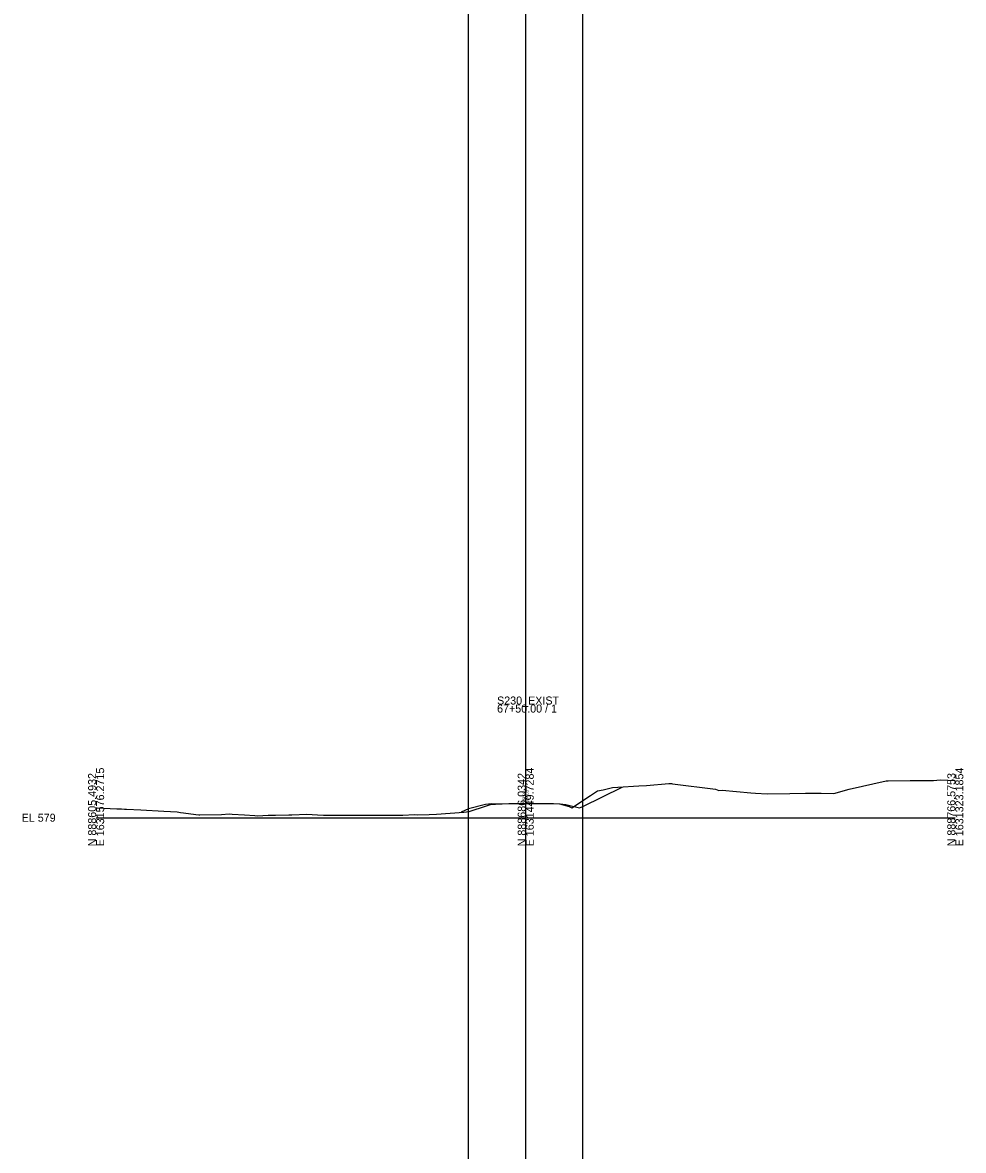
# Model space of a CAD drawing. Extents: x 1631115 to 1631443, y 885974 to 892071.
# Drawn here: x 1631114.8 to 1631443.3, y 886367.5 to 886761.1 of the extents above; entities that cross this region are included whole.
import ezdxf

# ---------------------------------------------------------------- set-up
doc = ezdxf.new("R2010")
doc.units = 0
for name, color, linetype in [('Default', 7, 'Continuous'), ('RD_GPK_XS_Cell', 7, 'Continuous'), ('RD_XS_EarthShd', 7, 'Continuous'), ('RD_XS_ExGround', 7, 'Continuous'), ('RD_XS_Pave', 7, 'Continuous'), ('RD_XS_TieSlope', 7, 'Continuous'), ('RD_XS_TX_Elev_EX', 7, 'Continuous'), ('RD_XS_TX_Elev_PR', 7, 'Continuous')]:
    doc.layers.add(name, color=color, linetype=linetype)

msp = doc.modelspace()

# ---------------------------------------------------------------- linework, layer by layer
at = {"layer": 'Default'}
for p, q in [((1631270.47, 885983.65), (1631270.47, 892068.63)), ((1631290.47, 885983.65), (1631290.47, 892068.63)), ((1631310.47, 885983.65), (1631310.47, 892068.63))]:
    msp.add_line(p, q, dxfattribs=at)
at = {"layer": 'RD_GPK_XS_Cell'}
for p, q in [((1631290.47, 886483.65), (1631290.47, 886523.14)), ((1631140.47, 886483.65), (1631290.47, 886483.65)), ((1631290.47, 886483.65), (1631440.47, 886483.65))]:
    msp.add_line(p, q, dxfattribs=at)
at = {"layer": 'RD_XS_EarthShd'}
for p, q in [((1631278.47, 886488.46), (1631276.47, 886488.3)), ((1631302.47, 886488.46), (1631304.47, 886488.3))]:
    msp.add_line(p, q, dxfattribs=at)
at = {"layer": 'RD_XS_ExGround'}
msp.add_lwpolyline([(1631140.47, 886487.07), (1631140.81, 886487.08), (1631147.73, 886486.8), (1631149.28, 886486.78), (1631150.38, 886486.68), (1631151.03, 886486.65), (1631156.14, 886486.4), (1631164.17, 886485.97), (1631168.76, 886485.65), (1631169.89, 886485.5), (1631170.97, 886485.38), (1631175.34, 886484.8), (1631176.37, 886484.67), (1631176.73, 886484.62), (1631184.26, 886484.74), (1631186.89, 886484.98), (1631187.94, 886484.94), (1631192.33, 886484.71), (1631195.84, 886484.43), (1631196.86, 886484.36), (1631200.5, 886484.5), (1631203.16, 886484.53), (1631207.76, 886484.62), (1631208.76, 886484.61), (1631214.06, 886484.9), (1631217.79, 886484.63), (1631219.92, 886484.58), (1631224.68, 886484.57), (1631233.4, 886484.49), (1631238.22, 886484.51), (1631240.87, 886484.56), (1631243.41, 886484.57), (1631247.52, 886484.55), (1631251.65, 886484.73), (1631252.82, 886484.67), (1631256.72, 886484.75), (1631259.27, 886484.86), (1631268.81, 886485.59), (1631270.76, 886485.76), (1631276.75, 886487.81), (1631278.2, 886488.24), (1631279.94, 886488.35), (1631284.57, 886488.61), (1631286.12, 886488.57), (1631290.47, 886488.58), (1631294.65, 886488.64), (1631298.78, 886488.63), (1631300.15, 886488.63), (1631302.22, 886488.45), (1631305.62, 886487.52), (1631306.54, 886487.1), (1631313.08, 886491.41), (1631315.55, 886493.08), (1631317.47, 886493.4), (1631320.79, 886494.15), (1631322.65, 886494.26), (1631329.91, 886494.73), (1631332.65, 886494.87), (1631340.49, 886495.54), (1631341.37, 886495.6), (1631341.75, 886495.5), (1631356.68, 886493.6), (1631357.95, 886493.17), (1631359.11, 886493.3), (1631369.12, 886492.34), (1631370.7, 886492.21), (1631374.83, 886492.04), (1631382.64, 886492.13), (1631388.13, 886492.24), (1631390.71, 886492.26), (1631393.64, 886492.17), (1631398.04, 886492.15), (1631403.4, 886493.56), (1631416.27, 886496.48), (1631417.08, 886496.53), (1631424.65, 886496.66), (1631425.46, 886496.65), (1631428.76, 886496.66), (1631431.83, 886496.68), (1631432.84, 886496.68), (1631435.18, 886496.82), (1631440.47, 886496.67)], dxfattribs=at)
at = {"layer": 'RD_XS_Pave'}
for p, q in [((1631278.47, 886488.46), (1631290.47, 886488.7)), ((1631290.47, 886488.7), (1631302.47, 886488.46))]:
    msp.add_line(p, q, dxfattribs=at)
at = {"layer": 'RD_XS_TieSlope'}
for p, q in [((1631310.47, 886487.51), (1631324.17, 886494.36)), ((1631270.47, 886486.8), (1631267.93, 886485.53)), ((1631276.47, 886488.3), (1631270.47, 886486.8)), ((1631304.47, 886488.3), (1631309.26, 886487.1)), ((1631309.26, 886487.1), (1631310.47, 886487.51))]:
    msp.add_line(p, q, dxfattribs=at)

# ---------------------------------------------------------------- texts
at = {"layer": 'RD_GPK_XS_Cell'}
for s, p in [('S230_EXIST', (1631280.47, 886523.14)), ('67+50.00 / 1', (1631280.47, 886520.34)), ('EL 579', (1631114.47, 886482.25))]:
    msp.add_text(s, height=2.8, dxfattribs=at).set_placement(p)
for s, p in [('N 888605.4932', (1631140.47, 886473.65)), ('E 1631576.2715', (1631143.27, 886473.65)), ('N 888686.0342', (1631290.47, 886473.65)), ('E 1631449.7284', (1631293.27, 886473.65)), ('N 888766.5753', (1631440.47, 886473.65)), ('E 1631323.1854', (1631443.27, 886473.65))]:
    msp.add_text(s, height=2.8, rotation=90, dxfattribs=at).set_placement(p)
at = {"layer": 'RD_XS_TX_Elev_EX'}
msp.add_text('583.93', height=1, rotation=90, dxfattribs=at).set_placement((1631290.37, 886488.68))
at = {"layer": 'RD_XS_TX_Elev_PR'}
msp.add_text(' 584.05', height=1, rotation=90, dxfattribs=at).set_placement((1631291.47, 886488.7))

doc.saveas('drawing.dxf')
